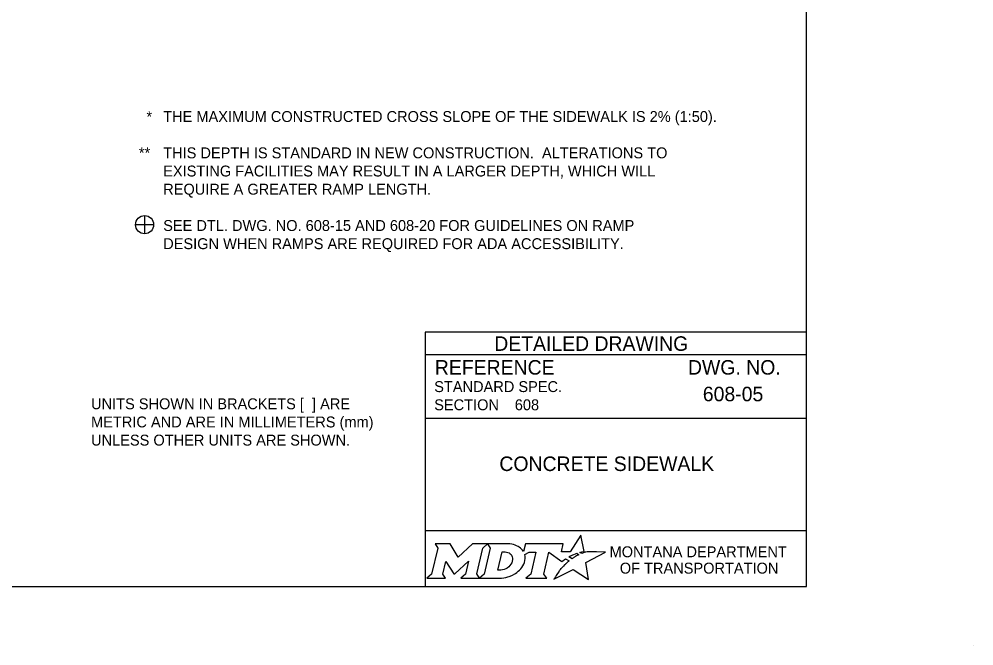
# Model space of a CAD drawing. Extents: x 49987.9 to 50021, y 49987.6 to 50011.4.
# Drawn here: x 50004.28 to 50009.54, y 49999.74 to 50003.19 of the extents above; entities that cross this region are included whole.
import ezdxf

# ---------------------------------------------------------------- set-up
doc = ezdxf.new("R2010")
doc.units = 0
doc.layers.add('Level 1', color=7, linetype='Continuous')
doc.layers.add('Level 2', color=7, linetype='Continuous')

msp = doc.modelspace()

# ---------------------------------------------------------------- linework, layer by layer
at = {"layer": 'Level 1'}
msp.add_line((50009.5374, 49999.7356), (50009.5374, 49999.7356), dxfattribs=at)
msp.add_lwpolyline([(50008.6146, 50011.2628), (50000.3356, 50011.2628), (50000.3356, 50000.0624), (50008.6146, 50000.0624)], close=True, dxfattribs=at)
at = {"layer": 'Level 2'}
for p, q in [((50004.9698, 50002.1043), (50004.9698, 50002.0043)), ((50005.0198, 50002.0543), (50004.9198, 50002.0543)), ((50008.6146, 50001.4624), (50006.5146, 50001.4624)), ((50006.5146, 50001.4624), (50006.5146, 50000.0624)), ((50008.6146, 50001.3374), (50006.5146, 50001.3374)), ((50008.6146, 50000.9874), (50006.5146, 50000.9874)), ((50008.6146, 50000.3693), (50006.5146, 50000.3693))]:
    msp.add_line(p, q, dxfattribs=at)
for points in [[(50007.3771, 50000.2447), (50007.3668, 50000.2503), (50007.3784, 50000.2531), (50007.39, 50000.2551), (50007.3726, 50000.3452), (50007.3131, 50000.2539), (50007.2658, 50000.2532), (50007.2761, 50000.2973), (50007.0669, 50000.2974), (50007.0568, 50000.2549), (50007.051, 50000.2632)], [(50006.5701, 50000.2974), (50006.5842, 50000.274), (50006.5507, 50000.1307), (50006.525, 50000.1082), (50006.6266, 50000.1082), (50006.6131, 50000.131), (50006.6293, 50000.2011), (50006.673, 50000.1321), (50006.6783, 50000.1321), (50006.7534, 50000.2016), (50006.737, 50000.1305), (50006.7123, 50000.1085), (50006.8139, 50000.1085), (50006.8001, 50000.1318), (50006.8333, 50000.2742)], [(50006.8333, 50000.2742), (50006.8586, 50000.2974), (50006.7762, 50000.2974), (50006.6966, 50000.2244), (50006.6521, 50000.2971), (50006.5701, 50000.2974)], [(50006.9722, 50000.2974), (50006.8586, 50000.2974), (50006.8733, 50000.2745), (50006.8394, 50000.1307), (50006.8139, 50000.1085), (50006.9245, 50000.1085)], [(50007.2527, 50000.1479), (50007.2374, 50000.1235), (50007.2327, 50000.116), (50007.2269, 50000.1074), (50007.2246, 50000.1031), (50007.3299, 50000.1562), (50007.4138, 50000.1011), (50007.4007, 50000.1938), (50007.5076, 50000.2522), (50007.4583, 50000.253), (50007.4282, 50000.2534), (50007.4074, 50000.2537), (50007.4006, 50000.2522), (50007.3957, 50000.251), (50007.3873, 50000.2487), (50007.3771, 50000.2447)], [(50006.9962, 50000.2107), (50006.995, 50000.2026), (50006.9918, 50000.1933), (50006.9876, 50000.1851), (50006.982, 50000.1776), (50006.9755, 50000.1707), (50006.9676, 50000.1644), (50006.9593, 50000.1597), (50006.9502, 50000.1558), (50006.9411, 50000.1535), (50006.9319, 50000.1526), (50006.916, 50000.1526), (50006.9396, 50000.2526), (50006.9556, 50000.2526), (50006.9632, 50000.252), (50006.9708, 50000.2501), (50006.9774, 50000.2471), (50006.9835, 50000.2429), (50006.9883, 50000.2379), (50006.992, 50000.2319), (50006.9947, 50000.2257), (50006.9963, 50000.2183), (50006.9963, 50000.2153), (50006.9962, 50000.2107)], [(50007.0636, 50000.2383), (50007.0882, 50000.2514), (50007.1251, 50000.2514), (50007.0965, 50000.1309), (50007.069, 50000.1082), (50007.1852, 50000.1082), (50007.1682, 50000.1311), (50007.1964, 50000.2513), (50007.2677, 50000.1996), (50007.2888, 50000.2147), (50007.3085, 50000.2038)], [(50007.3267, 50000.2171), (50007.3243, 50000.2154), (50007.306, 50000.225), (50007.3163, 50000.2307), (50007.3204, 50000.2329), (50007.329, 50000.2369), (50007.3347, 50000.2395), (50007.3426, 50000.2425), (50007.3499, 50000.2452), (50007.3617, 50000.2378), (50007.3577, 50000.2357), (50007.3531, 50000.2332), (50007.3489, 50000.231), (50007.3439, 50000.2281), (50007.342, 50000.227), (50007.3393, 50000.2254), (50007.3368, 50000.224), (50007.3345, 50000.2224), (50007.3319, 50000.2206), (50007.3292, 50000.2188), (50007.3267, 50000.2171)], [(50007.2666, 50000.164), (50007.2666, 50000.164)], [(50006.9702, 50000.1158), (50006.9786, 50000.1184), (50006.9916, 50000.1238), (50007.012, 50000.1348)]]:
    msp.add_lwpolyline(points, dxfattribs=at)
msp.add_circle((50004.9698, 50002.0543), 0.05, dxfattribs=at)
for centre, radius, start, end in [((50006.9953, 50000.219), 0.0709, 339.5329, 15.8582), ((50006.9513, 50000.2363), 0.1183, 300.9103, 339.1383)]:
    msp.add_arc(centre, radius, start, end, dxfattribs=at)
for centre, major_axis, ratio, start_param, end_param in [((50006.9701, 50000.25), (0.0834, -0.0037), 0.568097, 0.61298, 1.570796), ((50007.0257, 50000.2573), (0.0361, -0.0295), 0.469099, 1.225588, 1.570796), ((50007.2974, 50000.1941), (-0.0112, -0.0097), 0.021651, 3.157348, 6.283185), ((50007.2597, 50000.1559), (-0.00694, -0.00806), 0.008222, 0, 3.137361), ((50007.2764, 50000.1742), (-0.0098, -0.0102), 0.016458, 3.141593, 6.279097), ((50006.9248, 50000.2568), (0, 0.1484), 0.987302, 3.139398, 3.456847)]:
    msp.add_ellipse(centre, major_axis=major_axis, ratio=ratio, start_param=start_param, end_param=end_param, dxfattribs=at)

# ---------------------------------------------------------------- texts
for s, height, p in [('*', 0.06, (50004.98, 50002.6188)), ('THE MAXIMUM CONSTRUCTED CROSS SLOPE OF THE SIDEWALK IS 2% (1:50).', 0.06, (50005.0723, 50002.6198)), ('**', 0.06, (50004.9384, 50002.4198)), ('THIS DEPTH IS STANDARD IN NEW CONSTRUCTION.  ALTERATIONS TO', 0.06, (50005.0723, 50002.4198)), ('EXISTING FACILITIES MAY RESULT IN A LARGER DEPTH, WHICH WILL', 0.06, (50005.0723, 50002.3198)), ('REQUIRE A GREATER RAMP LENGTH.', 0.06, (50005.0723, 50002.2198)), ('SEE DTL. DWG. NO. 608-15 AND 608-20 FOR GUIDELINES ON RAMP', 0.06, (50005.0723, 50002.0198)), ('DESIGN WHEN RAMPS ARE REQUIRED FOR ADA ACCESSIBILITY.', 0.06, (50005.0723, 50001.9198)), ('DETAILED DRAWING', 0.0799, (50006.8956, 50001.3599)), ('REFERENCE', 0.08, (50006.5682, 50001.229)), ('DWG. NO.', 0.08, (50007.9624, 50001.229)), ('STANDARD SPEC.', 0.06, (50006.5649, 50001.133)), ('608-05', 0.08, (50008.0443, 50001.0823)), ('UNITS SHOWN IN BRACKETS [  ] ARE ', 0.06, (50004.675, 50001.0384)), ('SECTION', 0.06, (50006.5649, 50001.033)), ('608', 0.06, (50007.0088, 50001.0329)), ('METRIC AND ARE IN MILLIMETERS (mm) ', 0.06, (50004.675, 50000.9384)), ('UNLESS OTHER UNITS ARE SHOWN.', 0.06, (50004.675, 50000.8384)), ('CONCRETE SIDEWALK', 0.08, (50006.9238, 50000.6983))]:
    msp.add_text(s, height=height, dxfattribs=at).set_placement(p)
for s, p in [('MONTANA DEPARTMENT', (50007.5308, 50000.2236)), ('OF TRANSPORTATION', (50007.587, 50000.1336))]:
    msp.add_text(s, height=0.06, rotation=360, dxfattribs=at).set_placement(p)

doc.saveas('drawing.dxf')
